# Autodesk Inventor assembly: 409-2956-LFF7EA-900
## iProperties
Created: 2010-09
Part Number: 409-2956-LFF7EA-900
Document SubType Name: Assembly
Designer: S. Boerckel
Mass: 2.71449e+06 g
Surface Area: 794951 cm^2
Volume: 404621 cm^3
Density: 6.70872 g/cm^3
Description: GENERAL ARRANGEMENT UNIT 298034
Material: ASSEMBLY
SMR: =<MATERIAL>
Author: S. Boerckel
Revision Number: 0
Title: GENERAL ARRANGEMENT UNIT-298034
